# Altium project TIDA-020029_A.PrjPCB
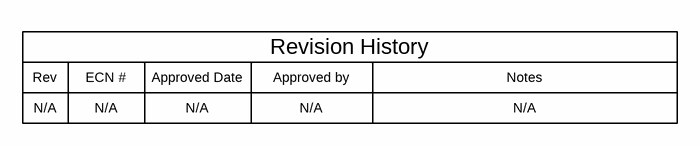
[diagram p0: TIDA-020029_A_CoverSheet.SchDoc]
TID: 020029; TechSupport: http://www.ti.com/support; SCH_Rev: A; PRJ_Title: Change in menu Project|Project Options|Parameters; PRJ_Number: TIDA-020029; PRJ_Engineer: Levan Bidzishvili; PRJ_Customer: Public Release; PCB_Rev: A; PCB_Layout: Levan Bidzishvili; CopyrightYear: 2019
4 sheets, 256 parts. Net scope: global (net labels, ports and power ports of the same name join across sheets).
Board file: TIDA-020029_A.PcbDoc
Sheets:
  TIDA-020029_A_CoverSheet.SchDoc
  TIDA-020029_A_1.SchDoc
  TIDA-020029_A_2.SchDoc
  TIDA-020029_A_3.SchDoc

## Sheet TIDA-020029_A_CoverSheet.SchDoc
size 431 x 279 mm; Date: Not shown in title block; ApprovedBy: Not shown in title block; CheckedBy: Not shown in title block; Author: Not shown in title block; CompanyName: Not shown in title block; Engineer: Not shown in title block; Organization: Not shown in title block; Address1: Not shown in title block; Address2: Not shown in title block; Address3: Not shown in title block; Address4: Not shown in title block; DocumentNumber: 1; Revision: Use project parameter SCH_Rev; SheetNumber: 1; SheetTotal: 4; PageSetup: Record=PageOptions¦CenterHorizontal=True¦CenterVertical=True¦PrintScale=1.00¦XCorrection=1.00¦YCorrection=1.00¦PrintKind=0¦BorderSize=5000000¦LeftOffset=0¦BottomOffset=0¦Orientation=2¦PaperLength=1000¦PaperWidth=1000¦Scale=100¦PaperSource=15¦PrintQuality=600¦MediaType=1¦DitherType=10¦PaperKind=Letter¦PrintScaleMode=1

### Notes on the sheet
- Rev
- N/A
- ECN #
- Approved Date
- Approved by
- Revision History
- Notes

## Sheet TIDA-020029_A_1.SchDoc
size 431 x 279 mm; Date: Not shown in title block; ApprovedBy: Not shown in title block; CheckedBy: Not shown in title block; Author: Not shown in title block; CompanyName: Not shown in title block; Engineer: Not shown in title block; Organization: Not shown in title block; Address1: Not shown in title block; Address2: Not shown in title block; Address3: Not shown in title block; Address4: Not shown in title block; DocumentNumber: 2; Revision: Use project parameter SCH_Rev; SheetNumber: 2; SheetTotal: 4
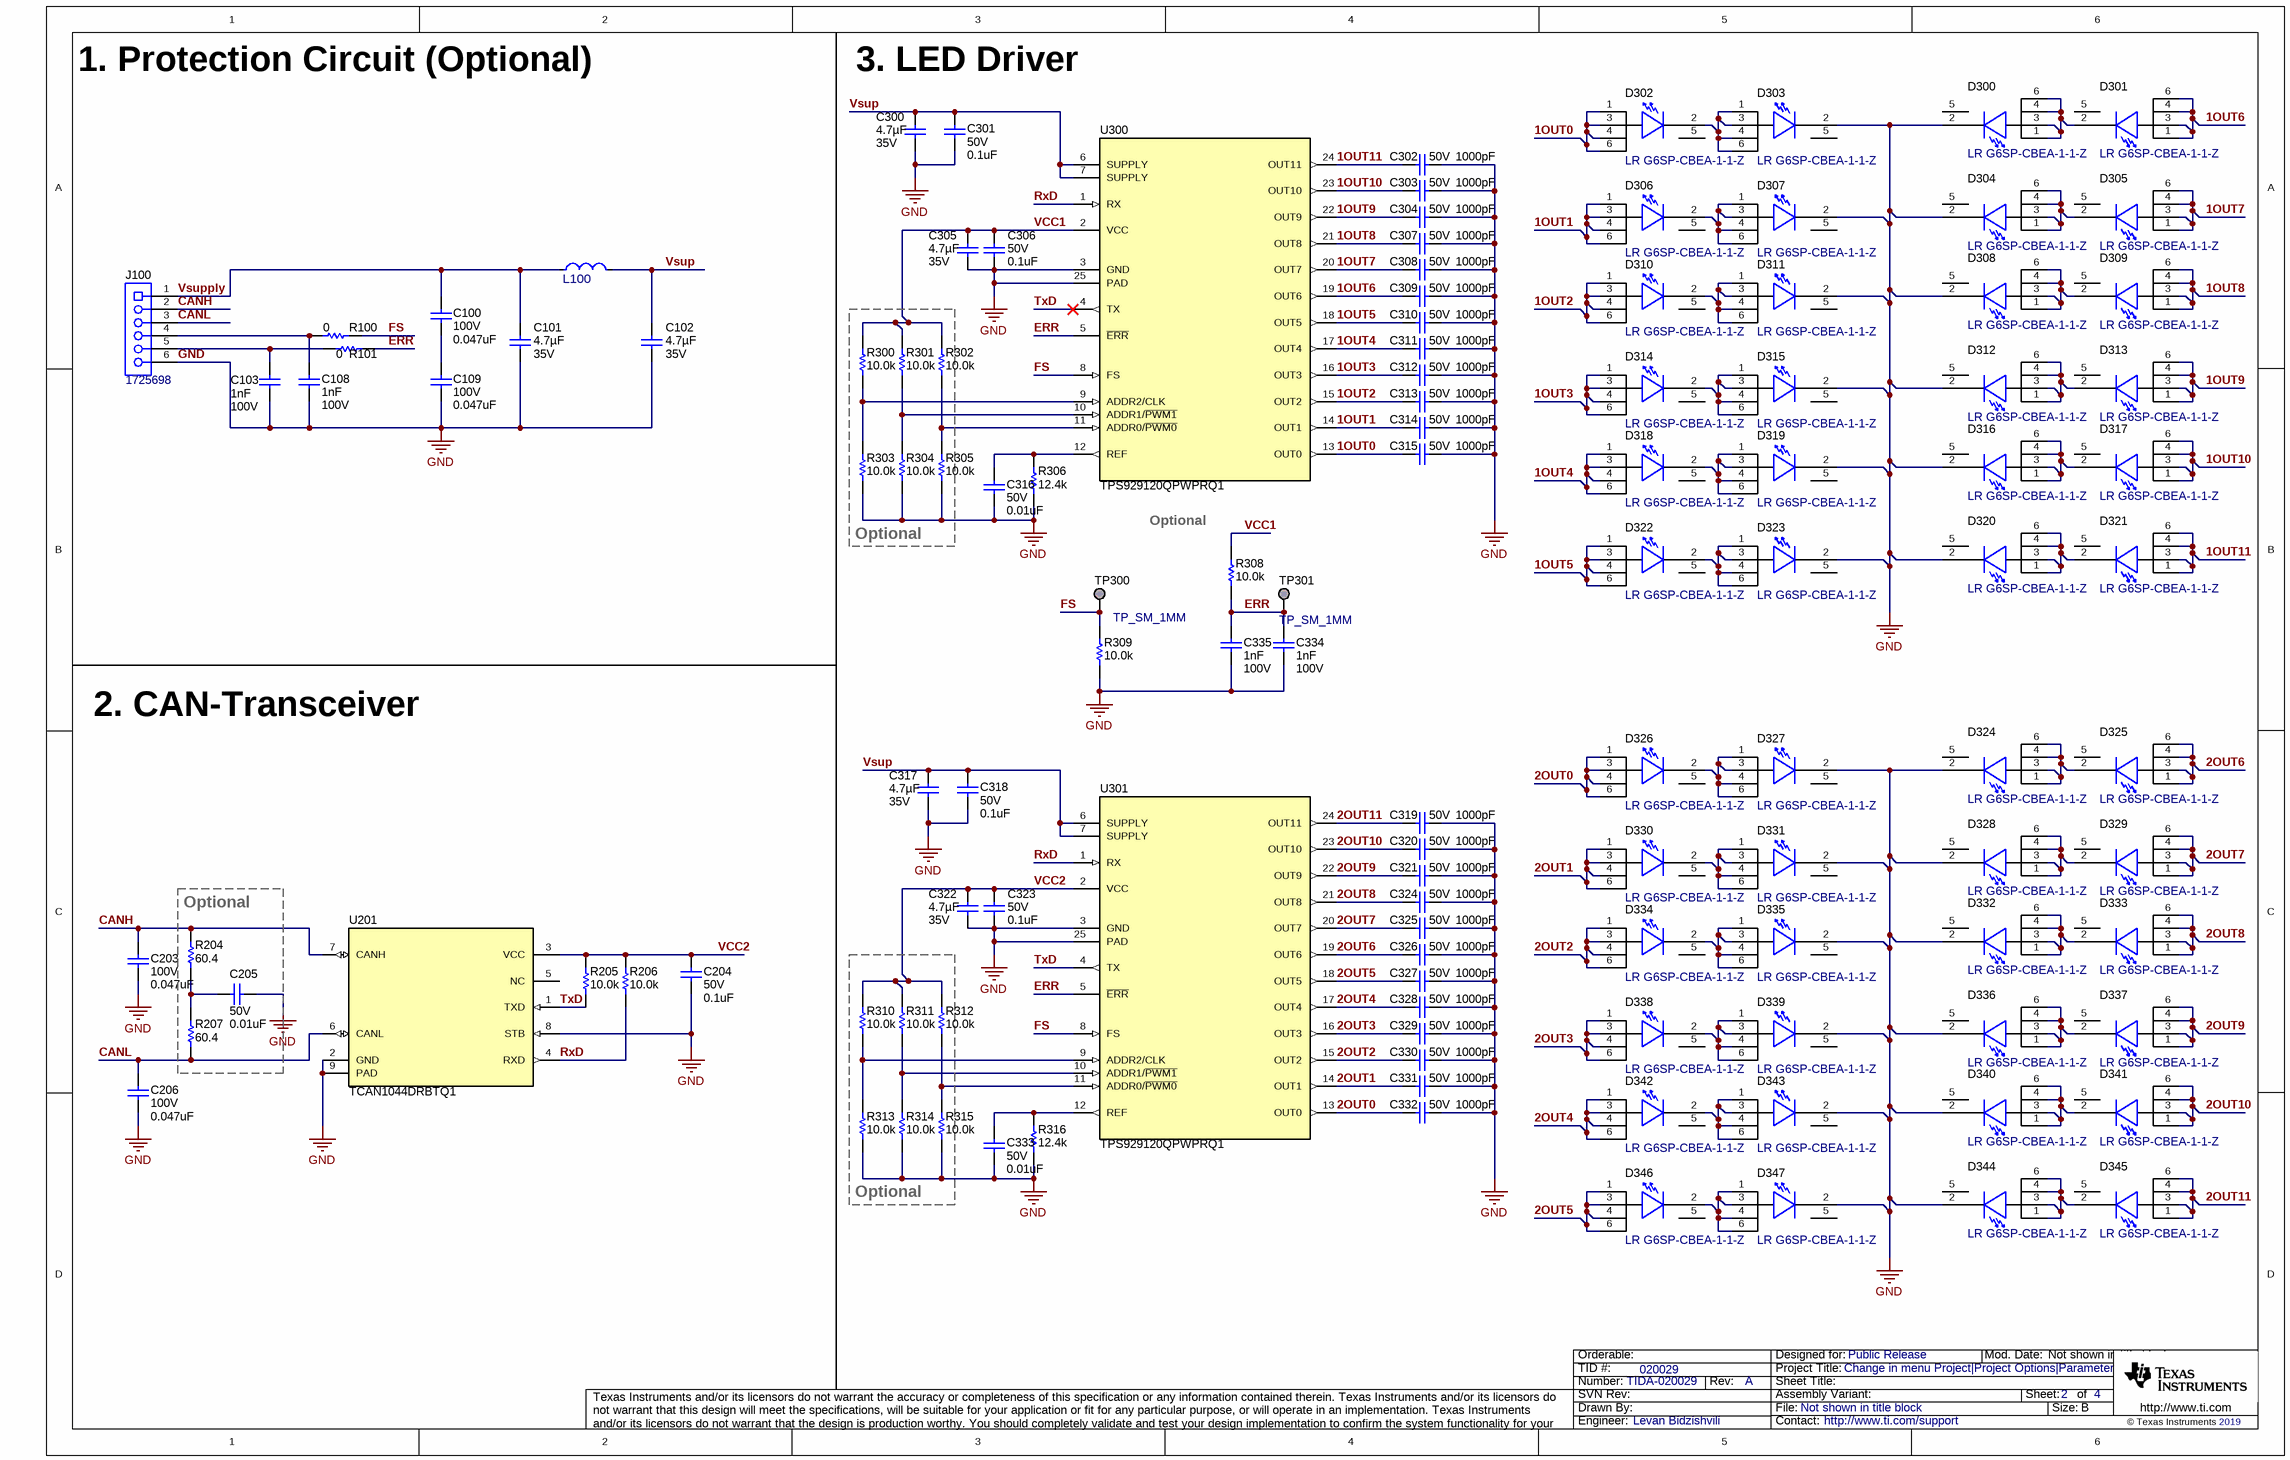
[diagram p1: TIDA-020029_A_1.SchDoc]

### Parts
C100  VDC_V: 100V  ValueDisplayed: 0.047uF  [0805L]  (hidden comment: CGA4J2X7R2A473K125AA)
C101  Cap_F: 4.7µF  VDC_V: 35V  [0805L]  (hidden comment: CGA4J1X7R1V475K125AC)
C102  Cap_F: 4.7µF  VDC_V: 35V  [0805L]  (hidden comment: CGA4J1X7R1V475K125AC)
C103  Cap_F: 1nF  VDC_V: 100V  [0603S]  (hidden comment: CGA3E2X7R2A102K080AA)
C108  Cap_F: 1nF  VDC_V: 100V  [0603S]  (hidden comment: CGA3E2X7R2A102K080AA)
C109  VDC_V: 100V  ValueDisplayed: 0.047uF  [0805L]  (hidden comment: CGA4J2X7R2A473K125AA)
C203  VDC_V: 100V  ValueDisplayed: 0.047uF  [0805_HV]  (hidden comment: CGA4J2X7R2A473K125AA)
C204  VDC_V: 50V  ValueDisplayed: 0.1uF  [0805_HV]  (hidden comment: C0805C104K5RACAUTO)
C205  VDC_V: 50V  ValueDisplayed: 0.01uF  [0603S]  (hidden comment: CGA3E2C0G1H103J080AA)
C206  VDC_V: 100V  ValueDisplayed: 0.047uF  [0805_HV]  (hidden comment: CGA4J2X7R2A473K125AA)
C300  Cap_F: 4.7µF  VDC_V: 35V  [0805L]  (hidden comment: CGA4J1X7R1V475K125AC)
C301  VDC_V: 50V  ValueDisplayed: 0.1uF  [0805L]  (hidden comment: CGA4J2X8R1H104M125AA)
C302  VDC_V: 50V  ValueDisplayed: 1000pF  [0402]  (hidden comment: CGA2B2C0G1H102J050BA)
C303  VDC_V: 50V  ValueDisplayed: 1000pF  [0402]  (hidden comment: CGA2B2C0G1H102J050BA)
C304  VDC_V: 50V  ValueDisplayed: 1000pF  [0402]  (hidden comment: CGA2B2C0G1H102J050BA)
C305  Cap_F: 4.7µF  VDC_V: 35V  [0805L]  (hidden comment: CGA4J1X7R1V475K125AC)
C306  VDC_V: 50V  ValueDisplayed: 0.1uF  [0805L]  (hidden comment: CGA4J2X8R1H104M125AA)
C307  VDC_V: 50V  ValueDisplayed: 1000pF  [0402]  (hidden comment: CGA2B2C0G1H102J050BA)
C308  VDC_V: 50V  ValueDisplayed: 1000pF  [0402]  (hidden comment: CGA2B2C0G1H102J050BA)
C309  VDC_V: 50V  ValueDisplayed: 1000pF  [0402]  (hidden comment: CGA2B2C0G1H102J050BA)
C310  VDC_V: 50V  ValueDisplayed: 1000pF  [0402]  (hidden comment: CGA2B2C0G1H102J050BA)
C311  VDC_V: 50V  ValueDisplayed: 1000pF  [0402]  (hidden comment: CGA2B2C0G1H102J050BA)
C312  VDC_V: 50V  ValueDisplayed: 1000pF  [0402]  (hidden comment: CGA2B2C0G1H102J050BA)
C313  VDC_V: 50V  ValueDisplayed: 1000pF  [0402]  (hidden comment: CGA2B2C0G1H102J050BA)
C314  VDC_V: 50V  ValueDisplayed: 1000pF  [0402]  (hidden comment: CGA2B2C0G1H102J050BA)
C315  VDC_V: 50V  ValueDisplayed: 1000pF  [0402]  (hidden comment: CGA2B2C0G1H102J050BA)
C316  VDC_V: 50V  ValueDisplayed: 0.01uF  [0603S]  (hidden comment: CGA3E2C0G1H103J080AA)
C317  Cap_F: 4.7µF  VDC_V: 35V  [0805L]  (hidden comment: CGA4J1X7R1V475K125AC)
C318  VDC_V: 50V  ValueDisplayed: 0.1uF  [0805L]  (hidden comment: CGA4J2X8R1H104M125AA)
C319  VDC_V: 50V  ValueDisplayed: 1000pF  [0402]  (hidden comment: CGA2B2C0G1H102J050BA)
C320  VDC_V: 50V  ValueDisplayed: 1000pF  [0402]  (hidden comment: CGA2B2C0G1H102J050BA)
C321  VDC_V: 50V  ValueDisplayed: 1000pF  [0402]  (hidden comment: CGA2B2C0G1H102J050BA)
C322  Cap_F: 4.7µF  VDC_V: 35V  [0805L]  (hidden comment: CGA4J1X7R1V475K125AC)
C323  VDC_V: 50V  ValueDisplayed: 0.1uF  [0805L]  (hidden comment: CGA4J2X8R1H104M125AA)
C324  VDC_V: 50V  ValueDisplayed: 1000pF  [0402]  (hidden comment: CGA2B2C0G1H102J050BA)
C325  VDC_V: 50V  ValueDisplayed: 1000pF  [0402]  (hidden comment: CGA2B2C0G1H102J050BA)
C326  VDC_V: 50V  ValueDisplayed: 1000pF  [0402]  (hidden comment: CGA2B2C0G1H102J050BA)
C327  VDC_V: 50V  ValueDisplayed: 1000pF  [0402]  (hidden comment: CGA2B2C0G1H102J050BA)
C328  VDC_V: 50V  ValueDisplayed: 1000pF  [0402]  (hidden comment: CGA2B2C0G1H102J050BA)
C329  VDC_V: 50V  ValueDisplayed: 1000pF  [0402]  (hidden comment: CGA2B2C0G1H102J050BA)
C330  VDC_V: 50V  ValueDisplayed: 1000pF  [0402]  (hidden comment: CGA2B2C0G1H102J050BA)
C331  VDC_V: 50V  ValueDisplayed: 1000pF  [0402]  (hidden comment: CGA2B2C0G1H102J050BA)
C332  VDC_V: 50V  ValueDisplayed: 1000pF  [0402]  (hidden comment: CGA2B2C0G1H102J050BA)
C333  VDC_V: 50V  ValueDisplayed: 0.01uF  [0603S]  (hidden comment: CGA3E2C0G1H103J080AA)
C334  Cap_F: 1nF  VDC_V: 100V  [0603S]  (hidden comment: CGA3E2X7R2A102K080AA)
C335  Cap_F: 1nF  VDC_V: 100V  [0603S]  (hidden comment: CGA3E2X7R2A102K080AA)
D300  LR G6SP-CBEA-1-1-Z  [LED_LR_G6SP]
D301  LR G6SP-CBEA-1-1-Z  [LED_LR_G6SP]
D302  LR G6SP-CBEA-1-1-Z  [LED_LR_G6SP]
D303  LR G6SP-CBEA-1-1-Z  [LED_LR_G6SP]
D304  LR G6SP-CBEA-1-1-Z  [LED_LR_G6SP]
D305  LR G6SP-CBEA-1-1-Z  [LED_LR_G6SP]
D306  LR G6SP-CBEA-1-1-Z  [LED_LR_G6SP]
D307  LR G6SP-CBEA-1-1-Z  [LED_LR_G6SP]
D308  LR G6SP-CBEA-1-1-Z  [LED_LR_G6SP]
D309  LR G6SP-CBEA-1-1-Z  [LED_LR_G6SP]
D310  LR G6SP-CBEA-1-1-Z  [LED_LR_G6SP]
D311  LR G6SP-CBEA-1-1-Z  [LED_LR_G6SP]
D312  LR G6SP-CBEA-1-1-Z  [LED_LR_G6SP]
D313  LR G6SP-CBEA-1-1-Z  [LED_LR_G6SP]
D314  LR G6SP-CBEA-1-1-Z  [LED_LR_G6SP]
D315  LR G6SP-CBEA-1-1-Z  [LED_LR_G6SP]
D316  LR G6SP-CBEA-1-1-Z  [LED_LR_G6SP]
D317  LR G6SP-CBEA-1-1-Z  [LED_LR_G6SP]
D318  LR G6SP-CBEA-1-1-Z  [LED_LR_G6SP]
D319  LR G6SP-CBEA-1-1-Z  [LED_LR_G6SP]
D320  LR G6SP-CBEA-1-1-Z  [LED_LR_G6SP]
D321  LR G6SP-CBEA-1-1-Z  [LED_LR_G6SP]
D322  LR G6SP-CBEA-1-1-Z  [LED_LR_G6SP]
D323  LR G6SP-CBEA-1-1-Z  [LED_LR_G6SP]
D324  LR G6SP-CBEA-1-1-Z  [LED_LR_G6SP]
D325  LR G6SP-CBEA-1-1-Z  [LED_LR_G6SP]
D326  LR G6SP-CBEA-1-1-Z  [LED_LR_G6SP]
D327  LR G6SP-CBEA-1-1-Z  [LED_LR_G6SP]
D328  LR G6SP-CBEA-1-1-Z  [LED_LR_G6SP]
D329  LR G6SP-CBEA-1-1-Z  [LED_LR_G6SP]
D330  LR G6SP-CBEA-1-1-Z  [LED_LR_G6SP]
D331  LR G6SP-CBEA-1-1-Z  [LED_LR_G6SP]
D332  LR G6SP-CBEA-1-1-Z  [LED_LR_G6SP]
D333  LR G6SP-CBEA-1-1-Z  [LED_LR_G6SP]
D334  LR G6SP-CBEA-1-1-Z  [LED_LR_G6SP]
D335  LR G6SP-CBEA-1-1-Z  [LED_LR_G6SP]
D336  LR G6SP-CBEA-1-1-Z  [LED_LR_G6SP]
D337  LR G6SP-CBEA-1-1-Z  [LED_LR_G6SP]
D338  LR G6SP-CBEA-1-1-Z  [LED_LR_G6SP]
D339  LR G6SP-CBEA-1-1-Z  [LED_LR_G6SP]
D340  LR G6SP-CBEA-1-1-Z  [LED_LR_G6SP]
D341  LR G6SP-CBEA-1-1-Z  [LED_LR_G6SP]
D342  LR G6SP-CBEA-1-1-Z  [LED_LR_G6SP]
D343  LR G6SP-CBEA-1-1-Z  [LED_LR_G6SP]
D344  LR G6SP-CBEA-1-1-Z  [LED_LR_G6SP]
D345  LR G6SP-CBEA-1-1-Z  [LED_LR_G6SP]
D346  LR G6SP-CBEA-1-1-Z  [LED_LR_G6SP]
D347  LR G6SP-CBEA-1-1-Z  [LED_LR_G6SP]
J100  1725698  [Phoenix_1725698]
L100  XEL3530-122MEC  [FP-XEL3530-122MEC_SMT_IND_3MM2_3MM5-MFG]  (value not drawn)
R100  ValueDisplayed: 0  [0603S]  (hidden comment: RCS06030000Z0EA)
R101  ValueDisplayed: 0  [0603S]  (hidden comment: RCS06030000Z0EA)
R204  ValueDisplayed: 60.4  [0805_HV]  (hidden comment: CRCW080560R4FKEA)
R205  ValueDisplayed: 10.0k  [0603S]  (hidden comment: RMCF0603FT10K0)
R206  ValueDisplayed: 10.0k  [0603S]  (hidden comment: RMCF0603FT10K0)
R207  ValueDisplayed: 60.4  [0805_HV]  (hidden comment: CRCW080560R4FKEA)
R300  ValueDisplayed: 10.0k  [0603S]  (hidden comment: RMCF0603FT10K0)
R301  ValueDisplayed: 10.0k  [0603S]  (hidden comment: RMCF0603FT10K0)
R302  ValueDisplayed: 10.0k  [0603S]  (hidden comment: RMCF0603FT10K0)
R303  ValueDisplayed: 10.0k  [0603S]  (hidden comment: RMCF0603FT10K0)
R304  ValueDisplayed: 10.0k  [0603S]  (hidden comment: RMCF0603FT10K0)
R305  ValueDisplayed: 10.0k  [0603S]  (hidden comment: RMCF0603FT10K0)
R306  ValueDisplayed: 12.4k  [0805_HV]  (hidden comment: ERJ-6ENF1242V)
R308  ValueDisplayed: 10.0k  [0603S]  (hidden comment: RMCF0603FT10K0)
R309  ValueDisplayed: 10.0k  [0603S]  (hidden comment: RMCF0603FT10K0)
R310  ValueDisplayed: 10.0k  [0603S]  (hidden comment: RMCF0603FT10K0)
R311  ValueDisplayed: 10.0k  [0603S]  (hidden comment: RMCF0603FT10K0)
R312  ValueDisplayed: 10.0k  [0603S]  (hidden comment: RMCF0603FT10K0)
R313  ValueDisplayed: 10.0k  [0603S]  (hidden comment: RMCF0603FT10K0)
R314  ValueDisplayed: 10.0k  [0603S]  (hidden comment: RMCF0603FT10K0)
R315  ValueDisplayed: 10.0k  [0603S]  (hidden comment: RMCF0603FT10K0)
R316  ValueDisplayed: 12.4k  [0805_HV]  (hidden comment: ERJ-6ENF1242V)
TP300  TP_SM_1MM  [TP_SM_1MM]  (no BOM)
TP301  TP_SM_1MM  [TP_SM_1MM]  (no BOM)
U201  TCAN1044DRBTQ1  [DRB0008F]
U300  TPS929120QPWPRQ1  [PWP0024P_N]
U301  TPS929120QPWPRQ1  [PWP0024P_N]

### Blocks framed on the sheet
Optional: R300-R305
Optional: C205 R204 R207
Optional: R310-R315

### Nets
GND: C101.2 C102.2 C103.2 C108.2 C109.2 C203.2 C204.2 C205.2 C206.2 C300.2 C301.2 C302.1 C303.1 C304.1 C305.2 C306.2 C307.1 C308.1 C309.1 C310.1 C311.1 C312.1 C313.1 C314.1 C315.1 C316.1 C317.2 C318.2 C319.1 C320.1 C321.1 C322.2 C323.2 C324.1 C325.1 C326.1 C327.1 C328.1 C329.1 C330.1 C331.1 C332.1 C333.1 C334.2 C335.2 D300.2(K) D303.2(K) D304.2(K) D307.2(K) D308.2(K) D311.2(K) D312.2(K) D315.2(K) D316.2(K) D319.2(K) D320.2(K) D323.2(K) D324.2(K) D327.2(K) D328.2(K) D331.2(K) D332.2(K) D335.2(K) D336.2(K) D339.2(K) D340.2(K) D343.2(K) D344.2(K) D347.2(K) J100.6 R303.1 R304.1 R305.1 R306.1 R309.1 R313.1 R314.1 R315.1 R316.1 U201.2(GND) U201.8(STB) U201.9(PAD) U300.3(GND) U300.25(PAD) U301.3(GND) U301.25(PAD)
1OUT0: C315.2 D302.1(A) D302.3(A) D302.4(A) D302.6(A) U300.13(OUT0)
1OUT1: C314.2 D306.1(A) D306.3(A) D306.4(A) D306.6(A) U300.14(OUT1)
1OUT2: C313.2 D310.1(A) D310.3(A) D310.4(A) D310.6(A) U300.15(OUT2)
1OUT3: C312.2 D314.1(A) D314.3(A) D314.4(A) D314.6(A) U300.16(OUT3)
1OUT4: C311.2 D318.1(A) D318.3(A) D318.4(A) D318.6(A) U300.17(OUT4)
1OUT5: C310.2 D322.1(A) D322.3(A) D322.4(A) D322.6(A) U300.18(OUT5)
1OUT6: C309.2 D301.1(A) D301.3(A) D301.4(A) D301.6(A) U300.19(OUT6)
1OUT7: C308.2 D305.1(A) D305.3(A) D305.4(A) D305.6(A) U300.20(OUT7)
1OUT8: C307.2 D309.1(A) D309.3(A) D309.4(A) D309.6(A) U300.21(OUT8)
1OUT9: C304.2 D313.1(A) D313.3(A) D313.4(A) D313.6(A) U300.22(OUT9)
1OUT10: C303.2 D317.1(A) D317.3(A) D317.4(A) D317.6(A) U300.23(OUT10)
1OUT11: C302.2 D321.1(A) D321.3(A) D321.4(A) D321.6(A) U300.24(OUT11)
2OUT0: C332.2 D326.1(A) D326.3(A) D326.4(A) D326.6(A) U301.13(OUT0)
2OUT1: C331.2 D330.1(A) D330.3(A) D330.4(A) D330.6(A) U301.14(OUT1)
2OUT2: C330.2 D334.1(A) D334.3(A) D334.4(A) D334.6(A) U301.15(OUT2)
2OUT3: C329.2 D338.1(A) D338.3(A) D338.4(A) D338.6(A) U301.16(OUT3)
2OUT4: C328.2 D342.1(A) D342.3(A) D342.4(A) D342.6(A) U301.17(OUT4)
2OUT5: C327.2 D346.1(A) D346.3(A) D346.4(A) D346.6(A) U301.18(OUT5)
2OUT6: C326.2 D325.1(A) D325.3(A) D325.4(A) D325.6(A) U301.19(OUT6)
2OUT7: C325.2 D329.1(A) D329.3(A) D329.4(A) D329.6(A) U301.20(OUT7)
2OUT8: C324.2 D333.1(A) D333.3(A) D333.4(A) D333.6(A) U301.21(OUT8)
2OUT9: C321.2 D337.1(A) D337.3(A) D337.4(A) D337.6(A) U301.22(OUT9)
2OUT10: C320.2 D341.1(A) D341.3(A) D341.4(A) D341.6(A) U301.23(OUT10)
2OUT11: C319.2 D345.1(A) D345.3(A) D345.4(A) D345.6(A) U301.24(OUT11)
CANH: C203.1 J100.2 R204.2 U201.7(CANH)
CANL: C206.1 J100.3 R207.1 U201.6(CANL)
ERR: C334.1 C335.1 R101.2 R308.1 TP301.1 U300.5(~{ERR}) U301.5(~{ERR})
FS: R100.2 R309.2 TP300.1 U300.8(FS) U301.8(FS)
RxD: R206.1 U201.4(RXD) U300.1(RX) U301.1(RX)
TxD: R205.1 U201.1(TXD) U300.4(TX) U301.4(TX)
VCC1: C305.1 C306.1 R300.2 R301.2 R302.2 R308.2 U300.2(VCC)
VCC2: C204.1 C322.1 C323.1 R205.2 R206.2 R310.2 R311.2 R312.2 U201.3(VCC) U301.2(VCC)
Vsup: C102.1 C300.1 C301.1 C317.1 C318.1 L100.2 U300.6(SUPPLY) U300.7(SUPPLY) U301.6(SUPPLY) U301.7(SUPPLY)
Vsupply: C100.1 C101.1 J100.1 L100.1
NetC100_2: C100.2 C109.1
NetC103_1: C103.1 J100.5 R101.1
NetC108_1: C108.1 J100.4 R100.1
NetC205_1: C205.1 R204.1 R207.2
NetC316_2: C316.2 R306.2 U300.12(REF)
NetC333_2: C333.2 R316.2 U301.12(REF)
NetD300_1: D300.1(A) D300.3(A) D300.4(A) D300.6(A) D301.2(K)
NetD302_2: D302.2(K) D303.1(A) D303.3(A) D303.4(A) D303.6(A)
NetD304_1: D304.1(A) D304.3(A) D304.4(A) D304.6(A) D305.2(K)
NetD306_2: D306.2(K) D307.1(A) D307.3(A) D307.4(A) D307.6(A)
NetD308_1: D308.1(A) D308.3(A) D308.4(A) D308.6(A) D309.2(K)
NetD310_2: D310.2(K) D311.1(A) D311.3(A) D311.4(A) D311.6(A)
NetD312_1: D312.1(A) D312.3(A) D312.4(A) D312.6(A) D313.2(K)
NetD314_2: D314.2(K) D315.1(A) D315.3(A) D315.4(A) D315.6(A)
NetD316_1: D316.1(A) D316.3(A) D316.4(A) D316.6(A) D317.2(K)
NetD318_2: D318.2(K) D319.1(A) D319.3(A) D319.4(A) D319.6(A)
NetD320_1: D320.1(A) D320.3(A) D320.4(A) D320.6(A) D321.2(K)
NetD322_2: D322.2(K) D323.1(A) D323.3(A) D323.4(A) D323.6(A)
NetD324_1: D324.1(A) D324.3(A) D324.4(A) D324.6(A) D325.2(K)
NetD326_2: D326.2(K) D327.1(A) D327.3(A) D327.4(A) D327.6(A)
NetD328_1: D328.1(A) D328.3(A) D328.4(A) D328.6(A) D329.2(K)
NetD330_2: D330.2(K) D331.1(A) D331.3(A) D331.4(A) D331.6(A)
NetD332_1: D332.1(A) D332.3(A) D332.4(A) D332.6(A) D333.2(K)
NetD334_2: D334.2(K) D335.1(A) D335.3(A) D335.4(A) D335.6(A)
NetD336_1: D336.1(A) D336.3(A) D336.4(A) D336.6(A) D337.2(K)
NetD338_2: D338.2(K) D339.1(A) D339.3(A) D339.4(A) D339.6(A)
NetD340_1: D340.1(A) D340.3(A) D340.4(A) D340.6(A) D341.2(K)
NetD342_2: D342.2(K) D343.1(A) D343.3(A) D343.4(A) D343.6(A)
NetD344_1: D344.1(A) D344.3(A) D344.4(A) D344.6(A) D345.2(K)
NetD346_2: D346.2(K) D347.1(A) D347.3(A) D347.4(A) D347.6(A)
NetR300_1: R300.1 R303.2 U300.9(ADDR2/CLK)
NetR301_1: R301.1 R304.2 U300.10(ADDR1/~{PWM1})
NetR302_1: R302.1 R305.2 U300.11(ADDR0/~{PWM0})
NetR310_1: R310.1 R313.2 U301.9(ADDR2/CLK)
NetR311_1: R311.1 R314.2 U301.10(ADDR1/~{PWM1})
NetR312_1: R312.1 R315.2 U301.11(ADDR0/~{PWM0})

Not connected (* = marked no-connect by the designer): D300 5(NC); D301 5(NC); D302 5(NC); D303 5(NC); D304 5(NC); D305 5(NC); D306 5(NC); D307 5(NC); D308 5(NC); D309 5(NC); D310 5(NC); D311 5(NC); D312 5(NC); D313 5(NC); D314 5(NC); D315 5(NC); D316 5(NC); D317 5(NC); D318 5(NC); D319 5(NC); D320 5(NC); D321 5(NC); D322 5(NC); D323 5(NC); D324 5(NC); D325 5(NC); D326 5(NC); D327 5(NC); D328 5(NC); D329 5(NC); D330 5(NC); D331 5(NC); D332 5(NC); D333 5(NC); D334 5(NC); D335 5(NC); D336 5(NC); D337 5(NC); D338 5(NC); D339 5(NC); D340 5(NC); D341 5(NC); D342 5(NC); D343 5(NC); D344 5(NC); D345 5(NC); D346 5(NC); D347 5(NC); U201 5(NC)

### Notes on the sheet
- 1. Protection Circuit (Optional)
- 3. LED Driver
- (near L100) 1.EMI Filter (BCI),CLC
  2. ERR & FS Pins to the connector (protection circuit)
- (near U300) VCC 50mA @ 5V
- Optional
- Reference current using an external resistor:
  1) K=500, Vref=1.22 => Ifull_range=49.2mA;
  2) K=62.5, Vref=1.22 => Ifull_range=6.15mA;
- default: Kref=62.5, Vref=1.22V. Kref has 2 bit programmability (2 bit register CONF_REFRANGE). I_fullrange=Vref / (Rref*Kref)
- UART-Interface Address Setting: Max 15 Devices (4bit address). EEPROM option EEP_INTADDR sets device address source (int or ext). EEP_INTADDR-High =>Internal 4bit address; EEP_INTADDR-Low =>External 3bit +1bit internal address
- 2. CAN-Transceiver
- programmable /ERR (open drain) pin
- ICC (Dominant, Rl=60Ohm,CL-open) = 70mA
  ICC (Dominant, Rl=50Ohm,CL-open) = 80mA
  ICC (Dominant with Bus fault, Rl,CL-open, CANH=CANL) = 180mA
  ICC (Recessive, Rl=50Ohm,CL,RCM-open) = 5mA

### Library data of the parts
C100 C109 C203 C206 = CMP-0007970-1: CAP, CERM, 0.047 uF, 100 V, +/- 10%, X7R, AEC-Q200 Grade 1, 0805; Manufacturer: TDK; TaMin_C: -55°C; ESR_ohm: 0.049089; Polarized: N; SizeAreaWB_mm2: 6.75; Value1: 0.049089 ohm; U/M: EA; TaMax_C: 125°C; SizeZ_mm: 1.45; SizeX_mm: 2; SizeY_mm: 1.25; Cap_Case: 0805; SizeArea_mm2: 2.5; AEC Qualified: Y; Cap_F: 47nF; IRMS_A: 963.171mA; AEC Grade: 1; AEC Category: Q200
C101 C102 C300 C305 C317 C322 = CMP-0007964-1: CAP, CERM, 4.7 uF, 35 V, +/- 10%, X7R, AEC-Q200 Grade 1, 0805; Manufacturer: TDK; TaMin_C: -55°C; ESR_ohm: 2.346m; Polarized: N; SizeAreaWB_mm2: 6.75; Value1: 0.002346 ohm; U/M: EA; Value: 4.7uF; TaMax_C: 125°C; SizeZ_mm: 1.45; SizeX_mm: 2; SizeY_mm: 1.25; Cap_Case: 0805; SizeArea_mm2: 2.5; AEC Qualified: Y; IRMS_A: 4.26021A; AEC Grade: 1; AEC Category: Q200
C103 C108 C334 C335 = CMP-0007081-1: CAP, CERM, 1000 pF, 100 V, +/- 10%, X7R, AEC-Q200 Grade 1, 0603; Manufacturer: TDK; TaMin_C: -55°C; ESR_ohm: 1.97137; Polarized: N; SizeAreaWB_mm2: 4.68; Value1: 1.97137 ohm; U/M: EA; Value: 1000pF; TaMax_C: 125°C; SizeZ_mm: 1; SizeX_mm: 1.6; SizeY_mm: 0.8; Cap_Case: 0603; SizeArea_mm2: 1.28; AEC Qualified: Y; IRMS_A: 305.705mA; AEC Category: Q200
C204 = CMP-0007725-1: CAP, CERM, 0.1 uF, 50 V, +/- 10%, X7R, AEC-Q200 Grade 0, 0805; Manufacturer: Kemet; TaMin_C: -55°C; Polarized: N; SizeAreaWB_mm2: 6.75; Value1: Unknown; U/M: EA; Value: 0.1uF; TaMax_C: 125°C; SizeZ_mm: 1.45; SizeX_mm: 2; SizeY_mm: 1.25; Cap_Case: 0805; SizeArea_mm2: 2.5; AEC Qualified: Y; Cap_F: 100nF; AEC Grade: 0; AEC Category: Q200
C205 C316 C333 = CMP-0007070-1: CAP, CERM, 0.01 uF, 50 V, +/- 5%, C0G/NP0, AEC-Q200 Grade 1, 0603; Manufacturer: TDK; TaMin_C: -55°C; Polarized: N; SizeAreaWB_mm2: 4.68; Value1: Unknown; U/M: EA; Value: 0.01uF; TaMax_C: 125°C; SizeZ_mm: 1; SizeX_mm: 1.6; SizeY_mm: 0.8; Cap_Case: 0603; SizeArea_mm2: 1.28; AEC Qualified: Y; Cap_F: 10nF; AEC Category: Q200
C301 C306 C318 C323 = CMP-0007971-1: CAP, CERM, 0.1 uF, 50 V, +/- 20%, X8R, AEC-Q200 Grade 0, 0805; Manufacturer: TDK; TaMin_C: -55°C; Polarized: N; SizeAreaWB_mm2: 6.75; Value1: Unknown; U/M: EA; Value: 0.1uF; TaMax_C: 150°C; SizeZ_mm: 1.45; SizeX_mm: 2; SizeY_mm: 1.25; Cap_Case: 0805; SizeArea_mm2: 2.5; AEC Qualified: Y; Cap_F: 100nF; AEC Grade: 0; AEC Category: Q200
C302-C304 C307-C315 C319-C321 C324-C332 = CMP-0006309-2: CAP, CERM, 1000 pF, 50 V, +/- 5%, C0G/NP0, AEC-Q200 Grade 1, 0402; Manufacturer: TDK; TaMin_C: -55°C; Polarized: N; SizeAreaWB_mm2: 3; Value1: Unknown; U/M: EA; Value: 1000pF; TaMax_C: 125°C; SizeZ_mm: 0.6; SizeX_mm: 1; SizeY_mm: 0.5; AEC Qualified: Y; Cap_F: 1nF; AEC Category: Q200
D300-D347 = CMP-0002833-3: LED, Red, SMD; Manufacturer: OSRAM; Vf_V: 2.1V; RJC_CperW: 110; Tjmax_C: 150°C; Io_A: 140mA; Value1: W
J100 = CMP-0055512-1: Terminal Block, 6x1, 2.54mm, TH; Manufacturer: Phoenix Contact; CNHeader: FALSE; Current_A: 6A; Cert_CSA: Y; Voltage_V: 160V; Row_Count: 1; Pitch_mm: 2.54; CT: TRUE
L100 = CMP-0087116-1: Shielded Power Inductors; Manufacturer: Coilcraft; AEC Grade: Grade 1; DCR_ohm: 0.0205; Isat: 2.5A; Ind_H: 1.2µH; AEC Qualified: Yes; Material: Composite; SizeZ_mm: 3mm; Irms: 4.2A
R100 R101 = CMP-0081973-1: RES, 0, 0%, 0.25 W, AEC-Q200 Grade 0, 0603; Manufacturer: Vishay-Dale; SizeAreaWB_mm2: 4.68; SizeArea_mm2: 1.28; AEC Qualified: Y; AEC Category: Q200; Value: 0; SizeZ_mm: 1; SizeY_mm: 0.8; Power_W: 250mW; Value2: 0.25W; SizeX_mm: 1.6
R204 R207 = CMP-0021368-3: RES, 60.4, 1%, 0.125 W, AEC-Q200 Grade 0, 0805; Manufacturer: Vishay-Dale; Power_W: 125mW; TempCo: 100 ppm/C; Value_Code: 60R4; Value: 60.4; EIA_Code: E96; SizeX_mm: 2; SizeY_mm: 1.25; SizeZ_mm: 1.45; Value2: 0.125W; SizeArea_mm2: 2.5; AEC Qualified: Y; VDC_V: 150V; AEC Category: Q200; AEC Grade: 0
R205 R206 R300-R305 R308-R315 = CMP-0023341-1: RES, 10.0 k, 1%, 0.1 W, AEC-Q200 Grade 0, 0603; Manufacturer: Stackpole Electronics Inc; Power_W: 100mW; TempCo: 100 ppm/C; Value_Code: 10k0; U/M: EA; Value: 10.0k; EIA_Code: E96; Res_ohm: 10k; SizeX_mm: 1.6; SizeY_mm: 0.8; SizeZ_mm: 1; Value2: 0.1W; SizeArea_mm2: 1.28; AEC Qualified: Y; VDC_V: 75V; AEC Grade: 0; AEC Category: Q200
R306 R316 = CMP-0021550-3: RES, 12.4 k, 1%, 0.125 W, AEC-Q200 Grade 0, 0805; Manufacturer: Panasonic; Power_W: 125mW; TempCo: 100 ppm/C; Value_Code: 12k4; Value: 12.4k; EIA_Code: E96; SizeX_mm: 2; SizeY_mm: 1.25; SizeZ_mm: 1.45; Value2: 0.125W; SizeArea_mm2: 2.5; AEC Qualified: Y; AEC Category: Q200; AEC Grade: 0; SizeAreaWB_mm2: 6.75
TP300 TP301 = CMP-0003825-1: 1mm Test Point, SMT; Manufacturer: Any
U201 = CMP-0079882-1: Automotive High Speed CAN Transceiver, DRB0008F (VSON-8); Alternate PartNumber: TCAN1044DRBRQ1; Alternate Manufacturer: Texas Instruments; SizeAreaWB_mm2: 16; SizeZ_mm: 1; SizeX_mm: 3; SizeArea_mm2: 9; CompType: IC; AEC Qualified: Y; AEC Category: Q200
U300 U301 = CMP-0084207-5: 12-Channel Automotive FlexLED Driver, PWP0024P (HTSSOP-24); Alternate Manufacturer: Texas Instruments; SizeAreaWB_mm2: 82.516; SizeX_mm: 6.42; SizeY_mm: 7.8; SizeZ_mm: 1.2; CompType: IC; AEC Category: Q200; SizeArea_mm2: 50.076; AEC Qualified: Y

## Sheet TIDA-020029_A_2.SchDoc
size 431 x 279 mm; Date: Not shown in title block; ApprovedBy: Not shown in title block; CheckedBy: Not shown in title block; Author: Not shown in title block; CompanyName: Not shown in title block; Engineer: Not shown in title block; Organization: Not shown in title block; Address1: Not shown in title block; Address2: Not shown in title block; Address3: Not shown in title block; Address4: Not shown in title block; DocumentNumber: 3; Revision: Use project parameter SCH_Rev; SheetNumber: 3; SheetTotal: 4; PageSetup: Record=PageOptions¦CenterHorizontal=True¦CenterVertical=True¦PrintScale=1.00¦XCorrection=1.00¦YCorrection=1.00¦PrintKind=0¦BorderSize=5000000¦LeftOffset=0¦BottomOffset=0¦Orientation=2¦PaperLength=1000¦PaperWidth=1000¦Scale=100¦PaperSource=15¦PrintQuality=600¦MediaType=1¦DitherType=10¦PaperKind=Letter¦PrintScaleMode=1
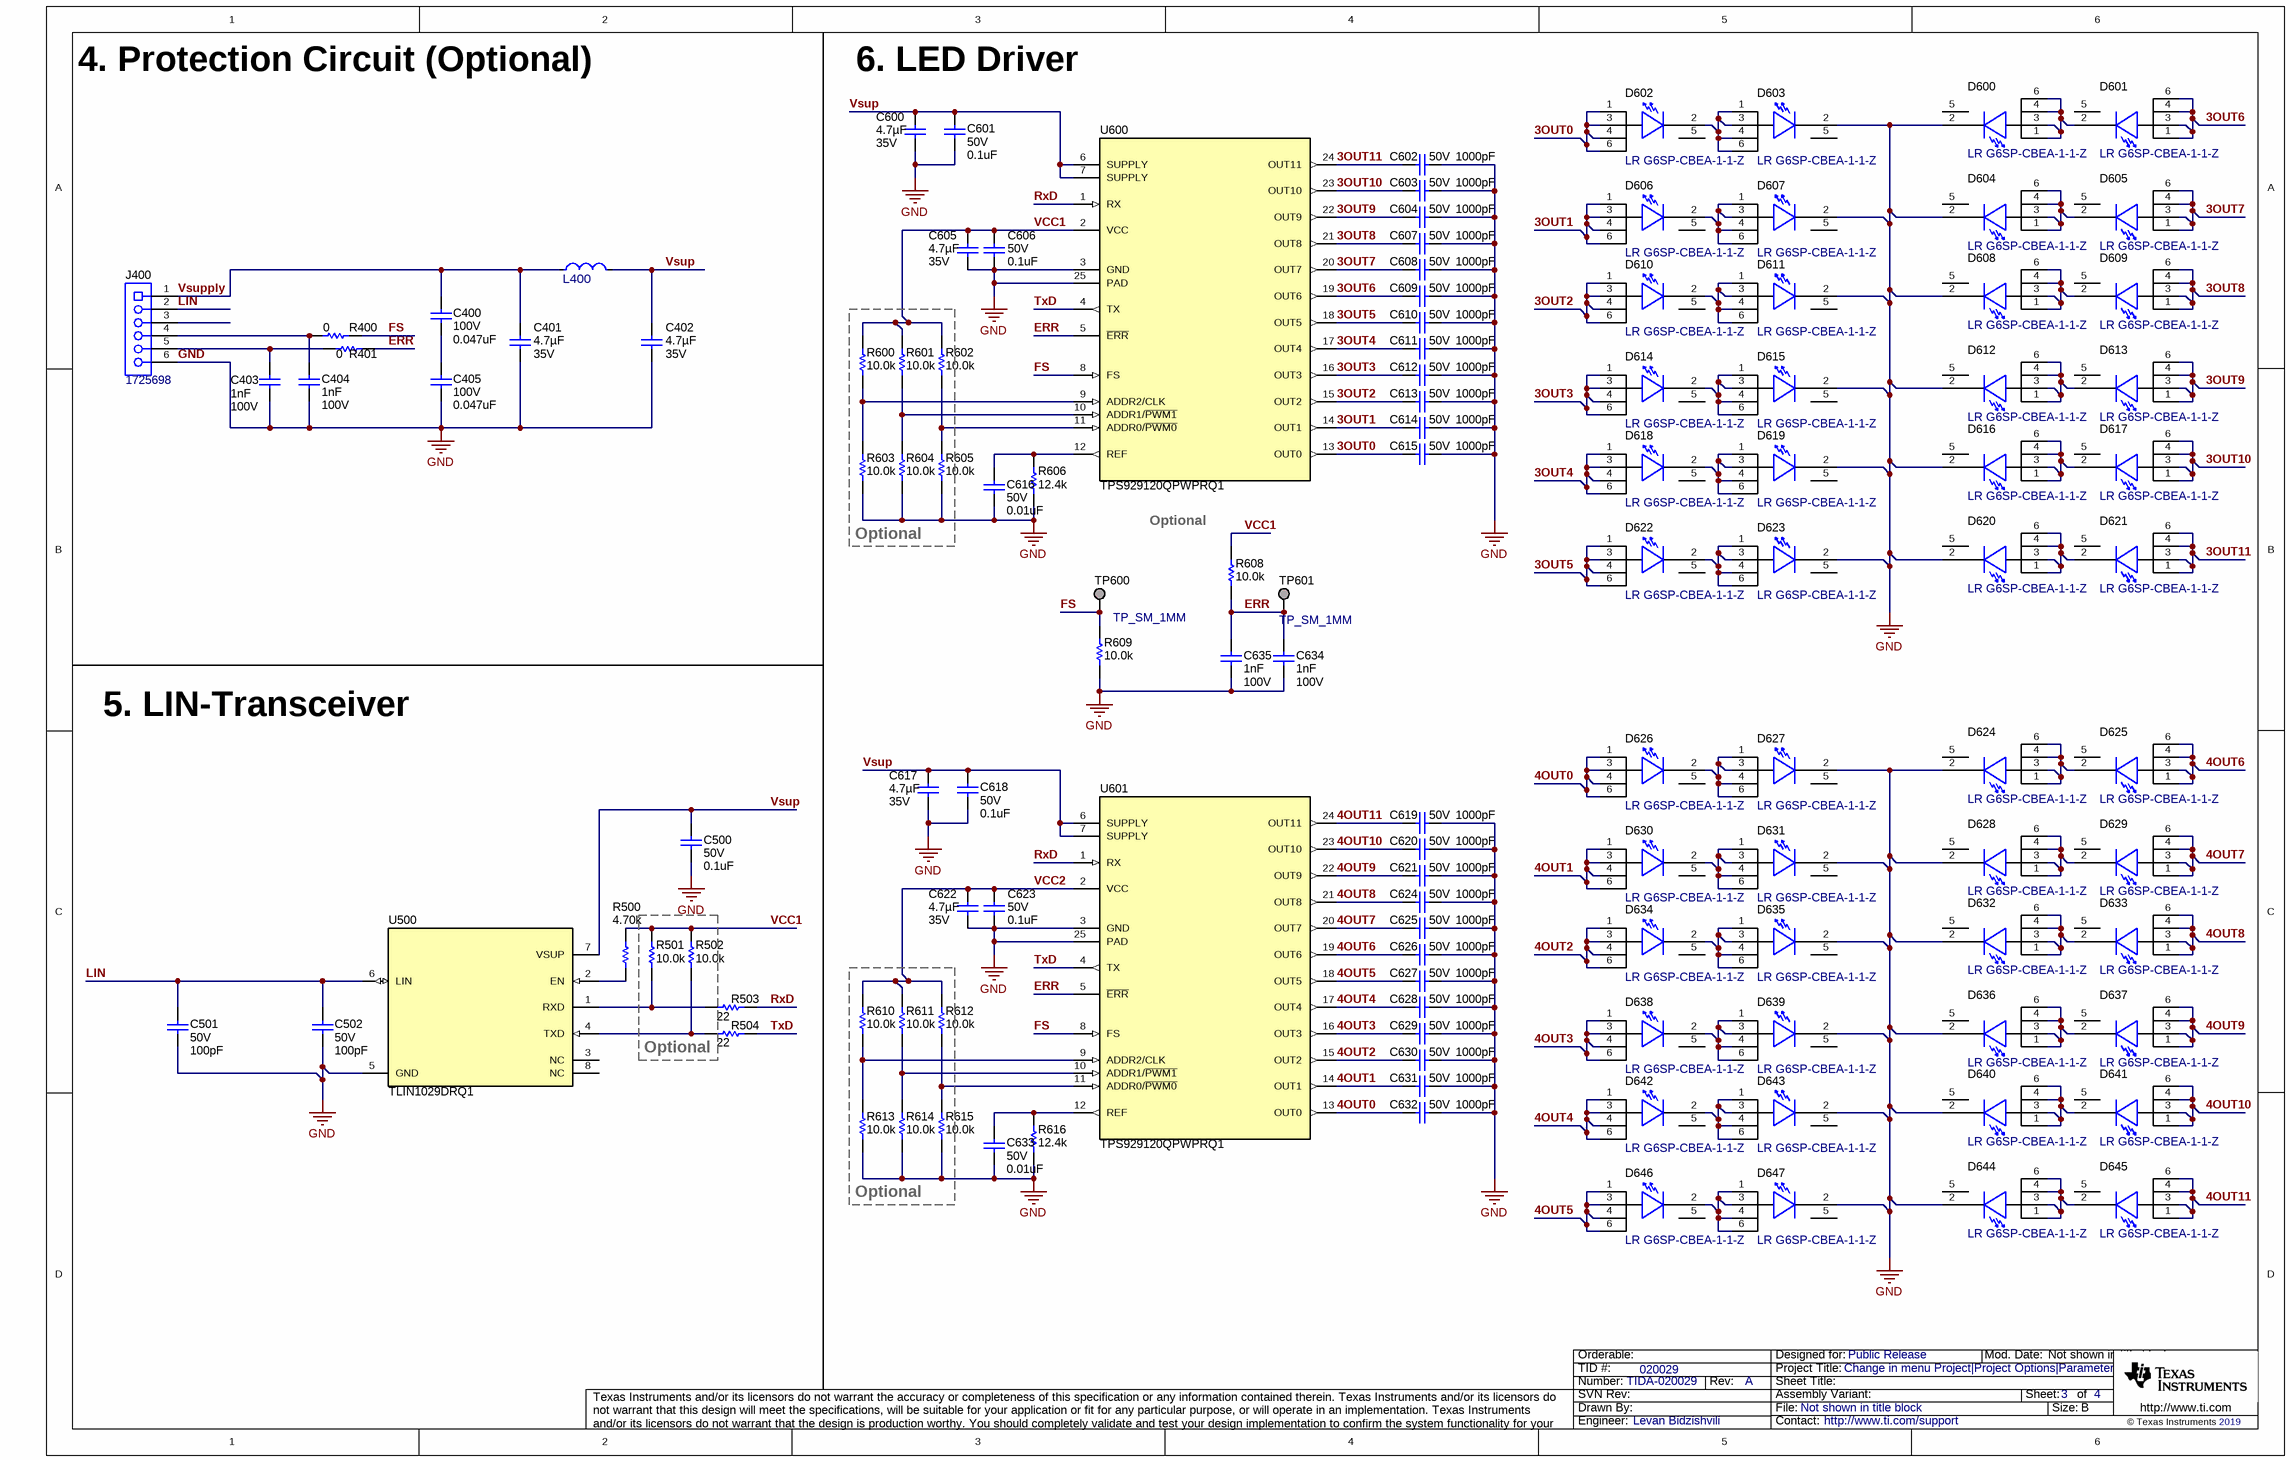
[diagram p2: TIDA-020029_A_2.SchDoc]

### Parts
C400  VDC_V: 100V  ValueDisplayed: 0.047uF  [0805L]  (hidden comment: CGA4J2X7R2A473K125AA)
C401  Cap_F: 4.7µF  VDC_V: 35V  [0805L]  (hidden comment: CGA4J1X7R1V475K125AC)
C402  Cap_F: 4.7µF  VDC_V: 35V  [0805L]  (hidden comment: CGA4J1X7R1V475K125AC)
C403  Cap_F: 1nF  VDC_V: 100V  [0603S]  (hidden comment: CGA3E2X7R2A102K080AA)
C404  Cap_F: 1nF  VDC_V: 100V  [0603S]  (hidden comment: CGA3E2X7R2A102K080AA)
C405  VDC_V: 100V  ValueDisplayed: 0.047uF  [0805L]  (hidden comment: CGA4J2X7R2A473K125AA)
C500  VDC_V: 50V  ValueDisplayed: 0.1uF  [0805L]  (hidden comment: CGA4J2X8R1H104M125AA)
C501  VDC_V: 50V  ValueDisplayed: 100pF  [0603S]  (hidden comment: CGA3E2NP01H101J080AA)
C502  VDC_V: 50V  ValueDisplayed: 100pF  [0603S]  (hidden comment: CGA3E2NP01H101J080AA)
C600  Cap_F: 4.7µF  VDC_V: 35V  [0805L]  (hidden comment: CGA4J1X7R1V475K125AC)
C601  VDC_V: 50V  ValueDisplayed: 0.1uF  [0805L]  (hidden comment: CGA4J2X8R1H104M125AA)
C602  VDC_V: 50V  ValueDisplayed: 1000pF  [0402]  (hidden comment: CGA2B2C0G1H102J050BA)
C603  VDC_V: 50V  ValueDisplayed: 1000pF  [0402]  (hidden comment: CGA2B2C0G1H102J050BA)
C604  VDC_V: 50V  ValueDisplayed: 1000pF  [0402]  (hidden comment: CGA2B2C0G1H102J050BA)
C605  Cap_F: 4.7µF  VDC_V: 35V  [0805L]  (hidden comment: CGA4J1X7R1V475K125AC)
C606  VDC_V: 50V  ValueDisplayed: 0.1uF  [0805L]  (hidden comment: CGA4J2X8R1H104M125AA)
C607  VDC_V: 50V  ValueDisplayed: 1000pF  [0402]  (hidden comment: CGA2B2C0G1H102J050BA)
C608  VDC_V: 50V  ValueDisplayed: 1000pF  [0402]  (hidden comment: CGA2B2C0G1H102J050BA)
C609  VDC_V: 50V  ValueDisplayed: 1000pF  [0402]  (hidden comment: CGA2B2C0G1H102J050BA)
C610  VDC_V: 50V  ValueDisplayed: 1000pF  [0402]  (hidden comment: CGA2B2C0G1H102J050BA)
C611  VDC_V: 50V  ValueDisplayed: 1000pF  [0402]  (hidden comment: CGA2B2C0G1H102J050BA)
C612  VDC_V: 50V  ValueDisplayed: 1000pF  [0402]  (hidden comment: CGA2B2C0G1H102J050BA)
C613  VDC_V: 50V  ValueDisplayed: 1000pF  [0402]  (hidden comment: CGA2B2C0G1H102J050BA)
C614  VDC_V: 50V  ValueDisplayed: 1000pF  [0402]  (hidden comment: CGA2B2C0G1H102J050BA)
C615  VDC_V: 50V  ValueDisplayed: 1000pF  [0402]  (hidden comment: CGA2B2C0G1H102J050BA)
C616  VDC_V: 50V  ValueDisplayed: 0.01uF  [0603S]  (hidden comment: CGA3E2C0G1H103J080AA)
C617  Cap_F: 4.7µF  VDC_V: 35V  [0805L]  (hidden comment: CGA4J1X7R1V475K125AC)
C618  VDC_V: 50V  ValueDisplayed: 0.1uF  [0805L]  (hidden comment: CGA4J2X8R1H104M125AA)
C619  VDC_V: 50V  ValueDisplayed: 1000pF  [0402]  (hidden comment: CGA2B2C0G1H102J050BA)
C620  VDC_V: 50V  ValueDisplayed: 1000pF  [0402]  (hidden comment: CGA2B2C0G1H102J050BA)
C621  VDC_V: 50V  ValueDisplayed: 1000pF  [0402]  (hidden comment: CGA2B2C0G1H102J050BA)
C622  Cap_F: 4.7µF  VDC_V: 35V  [0805L]  (hidden comment: CGA4J1X7R1V475K125AC)
C623  VDC_V: 50V  ValueDisplayed: 0.1uF  [0805L]  (hidden comment: CGA4J2X8R1H104M125AA)
C624  VDC_V: 50V  ValueDisplayed: 1000pF  [0402]  (hidden comment: CGA2B2C0G1H102J050BA)
C625  VDC_V: 50V  ValueDisplayed: 1000pF  [0402]  (hidden comment: CGA2B2C0G1H102J050BA)
C626  VDC_V: 50V  ValueDisplayed: 1000pF  [0402]  (hidden comment: CGA2B2C0G1H102J050BA)
C627  VDC_V: 50V  ValueDisplayed: 1000pF  [0402]  (hidden comment: CGA2B2C0G1H102J050BA)
C628  VDC_V: 50V  ValueDisplayed: 1000pF  [0402]  (hidden comment: CGA2B2C0G1H102J050BA)
C629  VDC_V: 50V  ValueDisplayed: 1000pF  [0402]  (hidden comment: CGA2B2C0G1H102J050BA)
C630  VDC_V: 50V  ValueDisplayed: 1000pF  [0402]  (hidden comment: CGA2B2C0G1H102J050BA)
C631  VDC_V: 50V  ValueDisplayed: 1000pF  [0402]  (hidden comment: CGA2B2C0G1H102J050BA)
C632  VDC_V: 50V  ValueDisplayed: 1000pF  [0402]  (hidden comment: CGA2B2C0G1H102J050BA)
C633  VDC_V: 50V  ValueDisplayed: 0.01uF  [0603S]  (hidden comment: CGA3E2C0G1H103J080AA)
C634  Cap_F: 1nF  VDC_V: 100V  [0603S]  (hidden comment: CGA3E2X7R2A102K080AA)
C635  Cap_F: 1nF  VDC_V: 100V  [0603S]  (hidden comment: CGA3E2X7R2A102K080AA)
D600  LR G6SP-CBEA-1-1-Z  [LED_LR_G6SP]
D601  LR G6SP-CBEA-1-1-Z  [LED_LR_G6SP]
D602  LR G6SP-CBEA-1-1-Z  [LED_LR_G6SP]
D603  LR G6SP-CBEA-1-1-Z  [LED_LR_G6SP]
D604  LR G6SP-CBEA-1-1-Z  [LED_LR_G6SP]
D605  LR G6SP-CBEA-1-1-Z  [LED_LR_G6SP]
D606  LR G6SP-CBEA-1-1-Z  [LED_LR_G6SP]
D607  LR G6SP-CBEA-1-1-Z  [LED_LR_G6SP]
D608  LR G6SP-CBEA-1-1-Z  [LED_LR_G6SP]
D609  LR G6SP-CBEA-1-1-Z  [LED_LR_G6SP]
D610  LR G6SP-CBEA-1-1-Z  [LED_LR_G6SP]
D611  LR G6SP-CBEA-1-1-Z  [LED_LR_G6SP]
D612  LR G6SP-CBEA-1-1-Z  [LED_LR_G6SP]
D613  LR G6SP-CBEA-1-1-Z  [LED_LR_G6SP]
D614  LR G6SP-CBEA-1-1-Z  [LED_LR_G6SP]
D615  LR G6SP-CBEA-1-1-Z  [LED_LR_G6SP]
D616  LR G6SP-CBEA-1-1-Z  [LED_LR_G6SP]
D617  LR G6SP-CBEA-1-1-Z  [LED_LR_G6SP]
D618  LR G6SP-CBEA-1-1-Z  [LED_LR_G6SP]
D619  LR G6SP-CBEA-1-1-Z  [LED_LR_G6SP]
D620  LR G6SP-CBEA-1-1-Z  [LED_LR_G6SP]
D621  LR G6SP-CBEA-1-1-Z  [LED_LR_G6SP]
D622  LR G6SP-CBEA-1-1-Z  [LED_LR_G6SP]
D623  LR G6SP-CBEA-1-1-Z  [LED_LR_G6SP]
D624  LR G6SP-CBEA-1-1-Z  [LED_LR_G6SP]
D625  LR G6SP-CBEA-1-1-Z  [LED_LR_G6SP]
D626  LR G6SP-CBEA-1-1-Z  [LED_LR_G6SP]
D627  LR G6SP-CBEA-1-1-Z  [LED_LR_G6SP]
D628  LR G6SP-CBEA-1-1-Z  [LED_LR_G6SP]
D629  LR G6SP-CBEA-1-1-Z  [LED_LR_G6SP]
D630  LR G6SP-CBEA-1-1-Z  [LED_LR_G6SP]
D631  LR G6SP-CBEA-1-1-Z  [LED_LR_G6SP]
D632  LR G6SP-CBEA-1-1-Z  [LED_LR_G6SP]
D633  LR G6SP-CBEA-1-1-Z  [LED_LR_G6SP]
D634  LR G6SP-CBEA-1-1-Z  [LED_LR_G6SP]
D635  LR G6SP-CBEA-1-1-Z  [LED_LR_G6SP]
D636  LR G6SP-CBEA-1-1-Z  [LED_LR_G6SP]
D637  LR G6SP-CBEA-1-1-Z  [LED_LR_G6SP]
D638  LR G6SP-CBEA-1-1-Z  [LED_LR_G6SP]
D639  LR G6SP-CBEA-1-1-Z  [LED_LR_G6SP]
D640  LR G6SP-CBEA-1-1-Z  [LED_LR_G6SP]
D641  LR G6SP-CBEA-1-1-Z  [LED_LR_G6SP]
D642  LR G6SP-CBEA-1-1-Z  [LED_LR_G6SP]
D643  LR G6SP-CBEA-1-1-Z  [LED_LR_G6SP]
D644  LR G6SP-CBEA-1-1-Z  [LED_LR_G6SP]
D645  LR G6SP-CBEA-1-1-Z  [LED_LR_G6SP]
D646  LR G6SP-CBEA-1-1-Z  [LED_LR_G6SP]
D647  LR G6SP-CBEA-1-1-Z  [LED_LR_G6SP]
J400  1725698  [Phoenix_1725698]
L400  XEL3530-122MEC  [FP-XEL3530-122MEC_SMT_IND_3MM2_3MM5-MFG]  (value not drawn)
R400  ValueDisplayed: 0  [0603S]  (hidden comment: RCS06030000Z0EA)
R401  ValueDisplayed: 0  [0603S]  (hidden comment: RCS06030000Z0EA)
R500  ValueDisplayed: 4.70k  [0805L]  (hidden comment: ERJ-P06F4701V)
R501  ValueDisplayed: 10.0k  [0603S]  (hidden comment: RMCF0603FT10K0)
R502  ValueDisplayed: 10.0k  [0603S]  (hidden comment: RMCF0603FT10K0)
R503  ValueDisplayed: 22  [0603S]  (hidden comment: CRCW060322R0JNEA)
R504  ValueDisplayed: 22  [0603S]  (hidden comment: CRCW060322R0JNEA)
R600  ValueDisplayed: 10.0k  [0603S]  (hidden comment: RMCF0603FT10K0)
R601  ValueDisplayed: 10.0k  [0603S]  (hidden comment: RMCF0603FT10K0)
R602  ValueDisplayed: 10.0k  [0603S]  (hidden comment: RMCF0603FT10K0)
R603  ValueDisplayed: 10.0k  [0603S]  (hidden comment: RMCF0603FT10K0)
R604  ValueDisplayed: 10.0k  [0603S]  (hidden comment: RMCF0603FT10K0)
R605  ValueDisplayed: 10.0k  [0603S]  (hidden comment: RMCF0603FT10K0)
R606  ValueDisplayed: 12.4k  [0805_HV]  (hidden comment: ERJ-6ENF1242V)
R608  ValueDisplayed: 10.0k  [0603S]  (hidden comment: RMCF0603FT10K0)
R609  ValueDisplayed: 10.0k  [0603S]  (hidden comment: RMCF0603FT10K0)
R610  ValueDisplayed: 10.0k  [0603S]  (hidden comment: RMCF0603FT10K0)
R611  ValueDisplayed: 10.0k  [0603S]  (hidden comment: RMCF0603FT10K0)
R612  ValueDisplayed: 10.0k  [0603S]  (hidden comment: RMCF0603FT10K0)
R613  ValueDisplayed: 10.0k  [0603S]  (hidden comment: RMCF0603FT10K0)
R614  ValueDisplayed: 10.0k  [0603S]  (hidden comment: RMCF0603FT10K0)
R615  ValueDisplayed: 10.0k  [0603S]  (hidden comment: RMCF0603FT10K0)
R616  ValueDisplayed: 12.4k  [0805_HV]  (hidden comment: ERJ-6ENF1242V)
TP600  TP_SM_1MM  [TP_SM_1MM]  (no BOM)
TP601  TP_SM_1MM  [TP_SM_1MM]  (no BOM)
U500  TLIN1029DRQ1  [D0008A_N]
U600  TPS929120QPWPRQ1  [PWP0024P_N]
U601  TPS929120QPWPRQ1  [PWP0024P_N]

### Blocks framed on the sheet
Optional: R600-R605
Optional: R501 R502
Optional: R610-R615

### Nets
GND: C401.2 C402.2 C403.2 C404.2 C405.2 C500.2 C501.2 C502.2 C600.2 C601.2 C602.1 C603.1 C604.1 C605.2 C606.2 C607.1 C608.1 C609.1 C610.1 C611.1 C612.1 C613.1 C614.1 C615.1 C616.1 C617.2 C618.2 C619.1 C620.1 C621.1 C622.2 C623.2 C624.1 C625.1 C626.1 C627.1 C628.1 C629.1 C630.1 C631.1 C632.1 C633.1 C634.2 C635.2 D600.2(K) D603.2(K) D604.2(K) D607.2(K) D608.2(K) D611.2(K) D612.2(K) D615.2(K) D616.2(K) D619.2(K) D620.2(K) D623.2(K) D624.2(K) D627.2(K) D628.2(K) D631.2(K) D632.2(K) D635.2(K) D636.2(K) D639.2(K) D640.2(K) D643.2(K) D644.2(K) D647.2(K) J400.6 R603.1 R604.1 R605.1 R606.1 R609.1 R613.1 R614.1 R615.1 R616.1 U500.5(GND) U600.3(GND) U600.25(PAD) U601.3(GND) U601.25(PAD)
3OUT0: C615.2 D602.1(A) D602.3(A) D602.4(A) D602.6(A) U600.13(OUT0)
3OUT1: C614.2 D606.1(A) D606.3(A) D606.4(A) D606.6(A) U600.14(OUT1)
3OUT2: C613.2 D610.1(A) D610.3(A) D610.4(A) D610.6(A) U600.15(OUT2)
3OUT3: C612.2 D614.1(A) D614.3(A) D614.4(A) D614.6(A) U600.16(OUT3)
3OUT4: C611.2 D618.1(A) D618.3(A) D618.4(A) D618.6(A) U600.17(OUT4)
3OUT5: C610.2 D622.1(A) D622.3(A) D622.4(A) D622.6(A) U600.18(OUT5)
3OUT6: C609.2 D601.1(A) D601.3(A) D601.4(A) D601.6(A) U600.19(OUT6)
3OUT7: C608.2 D605.1(A) D605.3(A) D605.4(A) D605.6(A) U600.20(OUT7)
3OUT8: C607.2 D609.1(A) D609.3(A) D609.4(A) D609.6(A) U600.21(OUT8)
3OUT9: C604.2 D613.1(A) D613.3(A) D613.4(A) D613.6(A) U600.22(OUT9)
3OUT10: C603.2 D617.1(A) D617.3(A) D617.4(A) D617.6(A) U600.23(OUT10)
3OUT11: C602.2 D621.1(A) D621.3(A) D621.4(A) D621.6(A) U600.24(OUT11)
4OUT0: C632.2 D626.1(A) D626.3(A) D626.4(A) D626.6(A) U601.13(OUT0)
4OUT1: C631.2 D630.1(A) D630.3(A) D630.4(A) D630.6(A) U601.14(OUT1)
4OUT2: C630.2 D634.1(A) D634.3(A) D634.4(A) D634.6(A) U601.15(OUT2)
4OUT3: C629.2 D638.1(A) D638.3(A) D638.4(A) D638.6(A) U601.16(OUT3)
4OUT4: C628.2 D642.1(A) D642.3(A) D642.4(A) D642.6(A) U601.17(OUT4)
4OUT5: C627.2 D646.1(A) D646.3(A) D646.4(A) D646.6(A) U601.18(OUT5)
4OUT6: C626.2 D625.1(A) D625.3(A) D625.4(A) D625.6(A) U601.19(OUT6)
4OUT7: C625.2 D629.1(A) D629.3(A) D629.4(A) D629.6(A) U601.20(OUT7)
4OUT8: C624.2 D633.1(A) D633.3(A) D633.4(A) D633.6(A) U601.21(OUT8)
4OUT9: C621.2 D637.1(A) D637.3(A) D637.4(A) D637.6(A) U601.22(OUT9)
4OUT10: C620.2 D641.1(A) D641.3(A) D641.4(A) D641.6(A) U601.23(OUT10)
4OUT11: C619.2 D645.1(A) D645.3(A) D645.4(A) D645.6(A) U601.24(OUT11)
ERR: C634.1 C635.1 R401.2 R608.1 TP601.1 U600.5(~{ERR}) U601.5(~{ERR})
FS: R400.2 R609.2 TP600.1 U600.8(FS) U601.8(FS)
LIN: C501.1 C502.1 J400.2 U500.6(LIN)
RxD: R503.1 U600.1(RX) U601.1(RX)
TxD: R504.1 U600.4(TX) U601.4(TX)
VCC1: C605.1 C606.1 R500.1 R501.2 R502.2 R600.2 R601.2 R602.2 R608.2 U600.2(VCC)
VCC2: C622.1 C623.1 R610.2 R611.2 R612.2 U601.2(VCC)
Vsup: C402.1 C500.1 C600.1 C601.1 C617.1 C618.1 L400.2 U500.7(VSUP) U600.6(SUPPLY) U600.7(SUPPLY) U601.6(SUPPLY) U601.7(SUPPLY)
Vsupply: C400.1 C401.1 J400.1 L400.1
NetC400_2: C400.2 C405.1
NetC403_1: C403.1 J400.5 R401.1
NetC404_1: C404.1 J400.4 R400.1
NetC616_2: C616.2 R606.2 U600.12(REF)
NetC633_2: C633.2 R616.2 U601.12(REF)
NetD600_1: D600.1(A) D600.3(A) D600.4(A) D600.6(A) D601.2(K)
NetD602_2: D602.2(K) D603.1(A) D603.3(A) D603.4(A) D603.6(A)
NetD604_1: D604.1(A) D604.3(A) D604.4(A) D604.6(A) D605.2(K)
NetD606_2: D606.2(K) D607.1(A) D607.3(A) D607.4(A) D607.6(A)
NetD608_1: D608.1(A) D608.3(A) D608.4(A) D608.6(A) D609.2(K)
NetD610_2: D610.2(K) D611.1(A) D611.3(A) D611.4(A) D611.6(A)
NetD612_1: D612.1(A) D612.3(A) D612.4(A) D612.6(A) D613.2(K)
NetD614_2: D614.2(K) D615.1(A) D615.3(A) D615.4(A) D615.6(A)
NetD616_1: D616.1(A) D616.3(A) D616.4(A) D616.6(A) D617.2(K)
NetD618_2: D618.2(K) D619.1(A) D619.3(A) D619.4(A) D619.6(A)
NetD620_1: D620.1(A) D620.3(A) D620.4(A) D620.6(A) D621.2(K)
NetD622_2: D622.2(K) D623.1(A) D623.3(A) D623.4(A) D623.6(A)
NetD624_1: D624.1(A) D624.3(A) D624.4(A) D624.6(A) D625.2(K)
NetD626_2: D626.2(K) D627.1(A) D627.3(A) D627.4(A) D627.6(A)
NetD628_1: D628.1(A) D628.3(A) D628.4(A) D628.6(A) D629.2(K)
NetD630_2: D630.2(K) D631.1(A) D631.3(A) D631.4(A) D631.6(A)
NetD632_1: D632.1(A) D632.3(A) D632.4(A) D632.6(A) D633.2(K)
NetD634_2: D634.2(K) D635.1(A) D635.3(A) D635.4(A) D635.6(A)
NetD636_1: D636.1(A) D636.3(A) D636.4(A) D636.6(A) D637.2(K)
NetD638_2: D638.2(K) D639.1(A) D639.3(A) D639.4(A) D639.6(A)
NetD640_1: D640.1(A) D640.3(A) D640.4(A) D640.6(A) D641.2(K)
NetD642_2: D642.2(K) D643.1(A) D643.3(A) D643.4(A) D643.6(A)
NetD644_1: D644.1(A) D644.3(A) D644.4(A) D644.6(A) D645.2(K)
NetD646_2: D646.2(K) D647.1(A) D647.3(A) D647.4(A) D647.6(A)
NetR500_2: R500.2 U500.2(EN)
NetR501_1: R501.1 R503.2 U500.1(RXD)
NetR502_1: R502.1 R504.2 U500.4(TXD)
NetR600_1: R600.1 R603.2 U600.9(ADDR2/CLK)
NetR601_1: R601.1 R604.2 U600.10(ADDR1/~{PWM1})
NetR602_1: R602.1 R605.2 U600.11(ADDR0/~{PWM0})
NetR610_1: R610.1 R613.2 U601.9(ADDR2/CLK)
NetR611_1: R611.1 R614.2 U601.10(ADDR1/~{PWM1})
NetR612_1: R612.1 R615.2 U601.11(ADDR0/~{PWM0})

Not connected (* = marked no-connect by the designer): D600 5(NC); D601 5(NC); D602 5(NC); D603 5(NC); D604 5(NC); D605 5(NC); D606 5(NC); D607 5(NC); D608 5(NC); D609 5(NC); D610 5(NC); D611 5(NC); D612 5(NC); D613 5(NC); D614 5(NC); D615 5(NC); D616 5(NC); D617 5(NC); D618 5(NC); D619 5(NC); D620 5(NC); D621 5(NC); D622 5(NC); D623 5(NC); D624 5(NC); D625 5(NC); D626 5(NC); D627 5(NC); D628 5(NC); D629 5(NC); D630 5(NC); D631 5(NC); D632 5(NC); D633 5(NC); D634 5(NC); D635 5(NC); D636 5(NC); D637 5(NC); D638 5(NC); D639 5(NC); D640 5(NC); D641 5(NC); D642 5(NC); D643 5(NC); D644 5(NC); D645 5(NC); D646 5(NC); D647 5(NC); J400 3; U500 3(NC) 8(NC)

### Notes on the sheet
- 4. Protection Circuit (Optional)
- 6. LED Driver
- (near U600) VCC 50mA @ 5V
- EMI Filter (BCI)
- Optional
- Reference current using an external resistor:
  1) K=500, Vref=1.22 => Ifull_range=49.2mA;
  2) K=62.5, Vref=1.22 => Ifull_range=6.15mA;
- default: Kref=62.5, Vref=1.22V. Kref has 2 bit programmability (2 bit register CONF_REFRANGE). I_fullrange=Vref / (Rref*Kref)
- UART-Interface Address Setting: Max 15 Devices (4bit address). EEPROM option EEP_INTADDR sets device address source (int or ext). EEP_INTADDR-High =>Internal 4bit address; EEP_INTADDR-Low =>External 3bit +1bit internal address
- 5. LIN-Transceiver
- (near C501) Varistor
- EMI ferrit

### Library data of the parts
C400 C405 = CMP-0007970-1: as C100 on sheet TIDA-020029_A_1
C401 C402 C600 C605 C617 C622 = CMP-0007964-1: as C101 on sheet TIDA-020029_A_1
C403 C404 C634 C635 = CMP-0007081-1: as C103 on sheet TIDA-020029_A_1
C500 C601 C606 C618 C623 = CMP-0007971-1: as C301 on sheet TIDA-020029_A_1
C501 C502 = CMP-0007075-1: CAP, CERM, 100 pF, 50 V, +/- 5%, C0G/NP0, AEC-Q200 Grade 0, 0603; Manufacturer: TDK; TaMin_C: -55°C; Polarized: N; SizeAreaWB_mm2: 4.68; Value1: Unknown; U/M: EA; Value: 100pF; TaMax_C: 150°C; SizeZ_mm: 1; SizeX_mm: 1.6; SizeY_mm: 0.8; Cap_Case: 0603; SizeArea_mm2: 1.28; AEC Qualified: Y; AEC Grade: 0; AEC Category: Q200
C602-C604 C607-C615 C619-C621 C624-C632 = CMP-0006309-2: as C302 on sheet TIDA-020029_A_1
C616 C633 = CMP-0007070-1: as C205 on sheet TIDA-020029_A_1
D600-D647 = CMP-0002833-3: as D300 on sheet TIDA-020029_A_1
J400 = CMP-0055512-1: as J100 on sheet TIDA-020029_A_1
L400 = CMP-0087116-1: as L100 on sheet TIDA-020029_A_1
R400 R401 = CMP-0081973-1: as R100 on sheet TIDA-020029_A_1
R500 = CMP-0021852-1: RES, 4.70 k, 1%, 0.5 W, AEC-Q200 Grade 0, 0805; Manufacturer: Panasonic; Power_W: 500mW; TempCo: 100 ppm/C; Value_Code: 4k70; U/M: EA; Value: 4.70k; Res_ohm: 4.7k; SizeX_mm: 2; SizeY_mm: 1.25; SizeZ_mm: 1.45; Value2: 0.5W; SizeArea_mm2: 2.5; AEC Qualified: Y; VDC_V: 400V; AEC Grade: 0; AEC Category: Q200
R501 R502 R600-R605 R608-R615 = CMP-0023341-1: as R205 on sheet TIDA-020029_A_1
R503 R504 = CMP-0025758-4: RES, 22, 5%, 0.1 W, AEC-Q200 Grade 0, 0603; Manufacturer: Vishay-Dale; Power_W: 100mW; TempCo: 200 ppm/C; Value_Code: 22R0; Value: 22; EIA_Code: E24; SizeX_mm: 1.6; SizeY_mm: 0.8; SizeZ_mm: 1; Value2: 0.1W; SizeArea_mm2: 1.28; AEC Qualified: Y; VDC_V: 75V; AEC Category: Q200; AEC Grade: 0
R606 R616 = CMP-0021550-3: as R306 on sheet TIDA-020029_A_1
TP600 TP601 = CMP-0003825-1: 1mm Test Point, SMT; Manufacturer: Any
U500 = CMP-0079113-1: Local Interconnect Network (LIN) Transceiver with Dominant State Timeout, D0008A (SOIC-8); Alternate PartNumber: TLIN1029DQ1; Alternate Manufacturer: Texas Instruments; SizeAreaWB_mm2: 56.58; SizeZ_mm: 1.75; SizeX_mm: 4.9; SizeY_mm: 6.2; SizeArea_mm2: 30.38; CompType: IC; AEC Qualified: Y; AEC Category: Q200
U600 U601 = CMP-0084207-5: as U300 on sheet TIDA-020029_A_1

## Sheet TIDA-020029_A_3.SchDoc
size 431 x 279 mm; Date: Not shown in title block; ApprovedBy: Not shown in title block; CheckedBy: Not shown in title block; Author: Not shown in title block; CompanyName: Not shown in title block; Engineer: Not shown in title block; Organization: Not shown in title block; Address1: Not shown in title block; Address2: Not shown in title block; Address3: Not shown in title block; Address4: Not shown in title block; DocumentNumber: 4; Revision: Use project parameter SCH_Rev; SheetNumber: 4; SheetTotal: 4; PageSetup: Record=PageOptions¦CenterHorizontal=True¦CenterVertical=True¦PrintScale=1.00¦XCorrection=1.00¦YCorrection=1.00¦PrintKind=0¦BorderSize=5000000¦LeftOffset=0¦BottomOffset=0¦Orientation=2¦PaperLength=1000¦PaperWidth=1000¦Scale=100¦PaperSource=15¦PrintQuality=600¦MediaType=1¦DitherType=10¦PaperKind=Letter¦PrintScaleMode=1
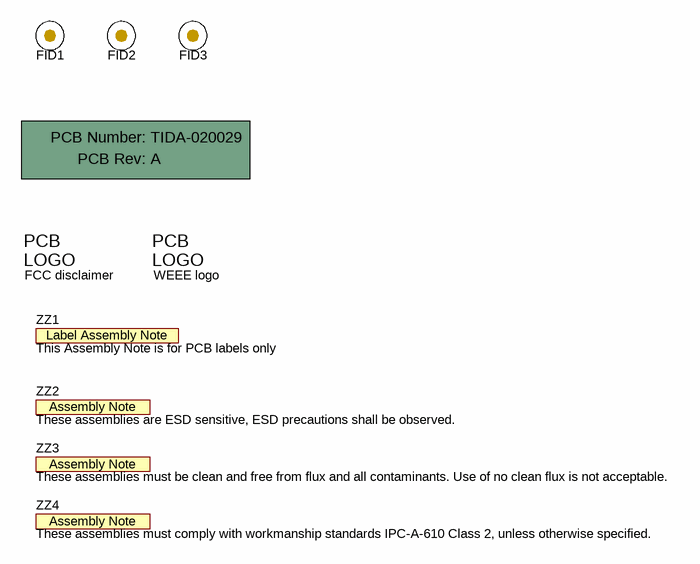
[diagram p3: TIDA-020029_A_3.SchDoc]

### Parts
!PCB1  Printed Circuit Board  (value not drawn)  (mechanical)
FID1  Fiducial  [Fiducial10-20]  (value not drawn)
FID2  Fiducial  [Fiducial10-20]  (value not drawn)
FID3  Fiducial  [Fiducial10-20]  (value not drawn)
Logo3  FCC disclaimer  [FCC_disclaimer]  (no BOM)
Logo4  WEEE logo  [WEEE_Minimum]  (no BOM)
ZZ1  This Assembly Note is for PCB labels only  [AssemblyNoteLabel]  (no BOM)
ZZ2  These assemblies are ESD sensitive, ESD precautions shall be observed.  [AssemblyNote]  (no BOM)
ZZ3  These assemblies must be clean and free from flux and all contaminants. Use of no clean flux is not acceptable.  [AssemblyNote]  (no BOM)
ZZ4  These assemblies must comply with workmanship standards IPC-A-610 Class 2, unless otherwise specified.  [AssemblyNote]  (no BOM)

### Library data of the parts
!PCB1 = CMP-0003618-2: Manufacturer: Any; PartNumber: TIDA-020029
FID1-FID3 = CMP-0077181-1: Fiducial mark.  There is nothing to buy or mount.
Logo3 = CMP-0074847-1: FCC_disclaimer; Library Reference: Logo
Logo4 = CMP-0074769-1
ZZ1 = CMP-0003616-3
ZZ2 = CMP-0077236-1
ZZ3 = CMP-0077237-1
ZZ4 = CMP-0077238-1

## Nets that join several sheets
GND: TIDA-020029_A_1 (86 pins), TIDA-020029_A_2 (83 pins)
ERR: TIDA-020029_A_1 (7 pins), TIDA-020029_A_2 (7 pins)
FS: TIDA-020029_A_1 (5 pins), TIDA-020029_A_2 (5 pins)
RxD: TIDA-020029_A_1 (R206.1 U201.4 U300.1 U301.1), TIDA-020029_A_2 (R503.1 U600.1 U601.1)
TxD: TIDA-020029_A_1 (R205.1 U201.1 U300.4 U301.4), TIDA-020029_A_2 (R504.1 U600.4 U601.4)
VCC1: TIDA-020029_A_1 (7 pins), TIDA-020029_A_2 (10 pins)
VCC2: TIDA-020029_A_1 (10 pins), TIDA-020029_A_2 (6 pins)
Vsup: TIDA-020029_A_1 (10 pins), TIDA-020029_A_2 (12 pins)
Vsupply: TIDA-020029_A_1 (C100.1 C101.1 J100.1 L100.1), TIDA-020029_A_2 (C400.1 C401.1 J400.1 L400.1)

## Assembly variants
001: not fitted FID1 FID2 FID3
